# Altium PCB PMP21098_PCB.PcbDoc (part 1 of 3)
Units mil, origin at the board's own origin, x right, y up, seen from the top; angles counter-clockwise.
Board outline 5551.18 x 2125.98 mil, 4 copper layers (Top Layer, Signal Layer 1, Signal Layer 2, Bottom Layer), stack 61.6 mil thick; 197 components, 100 nets, 482 pads, 134 vias.
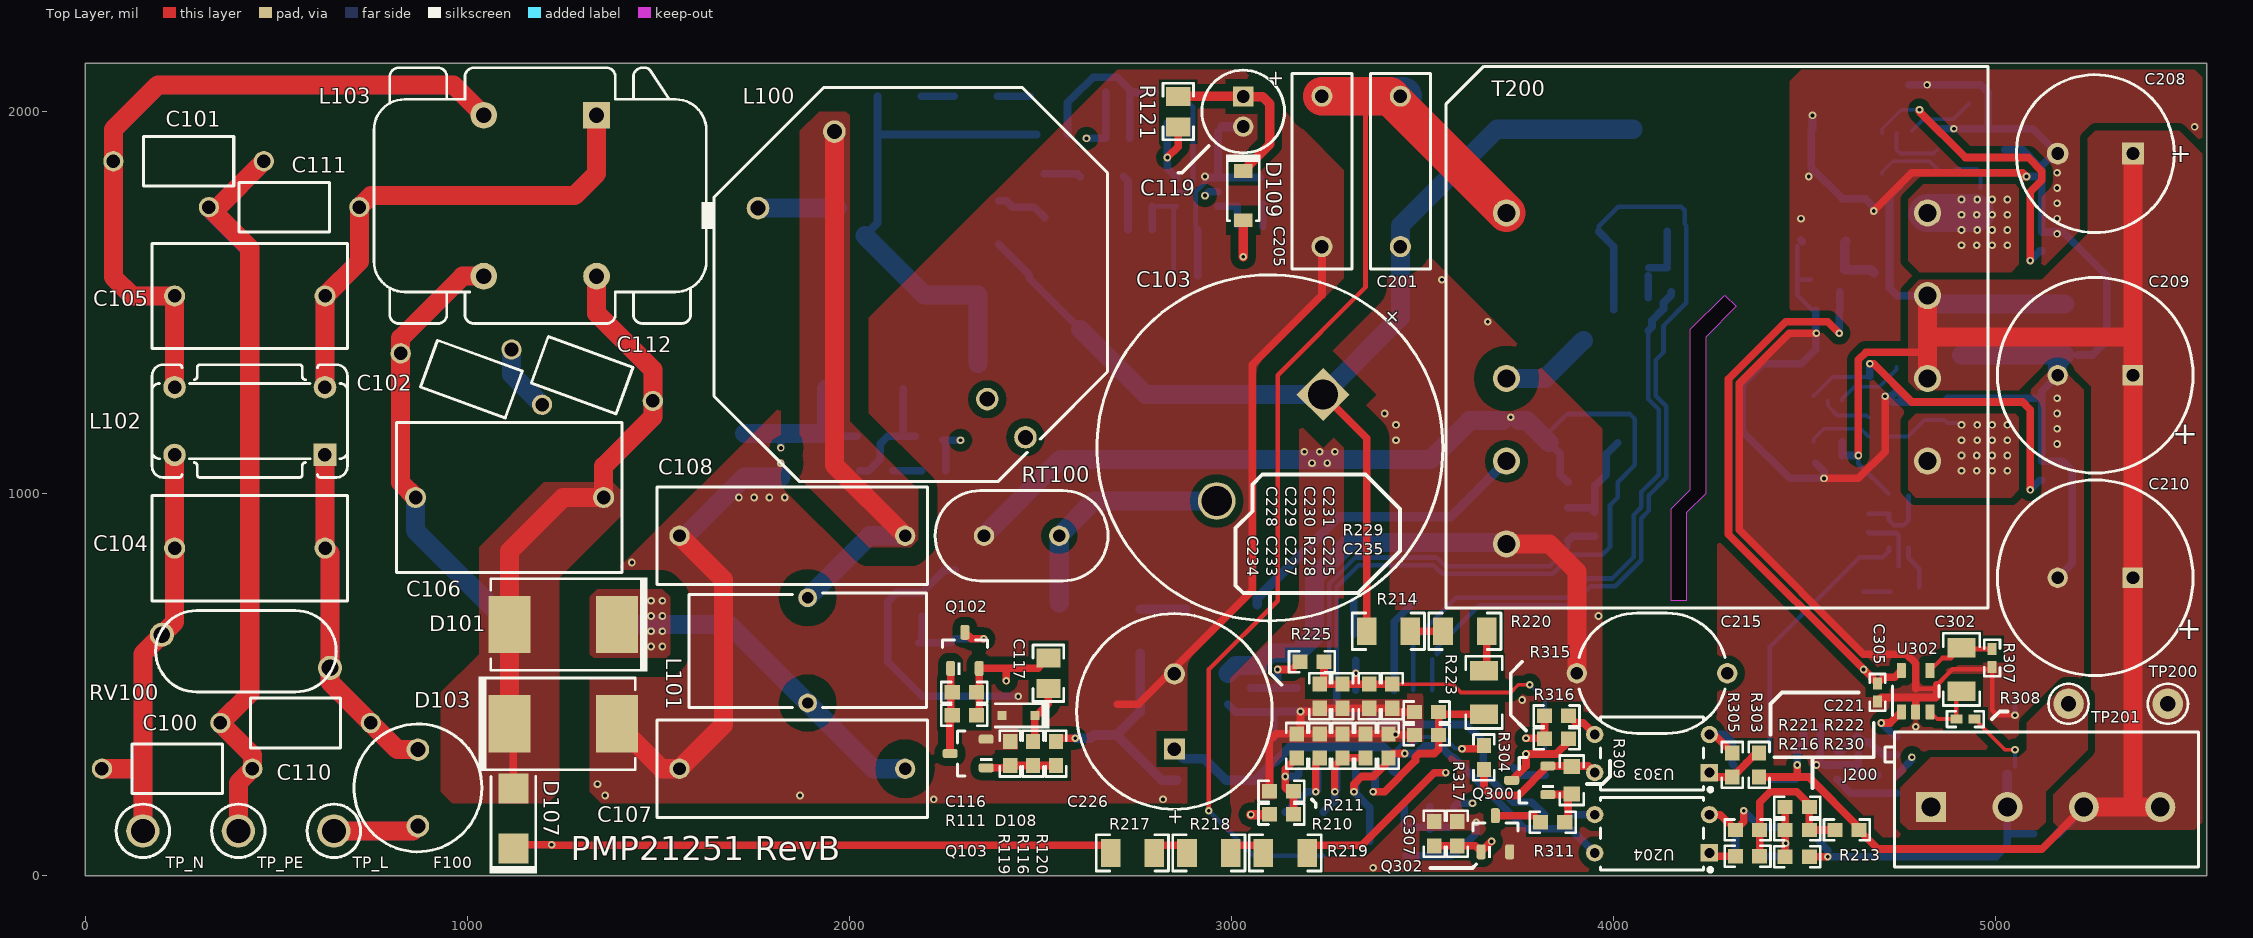
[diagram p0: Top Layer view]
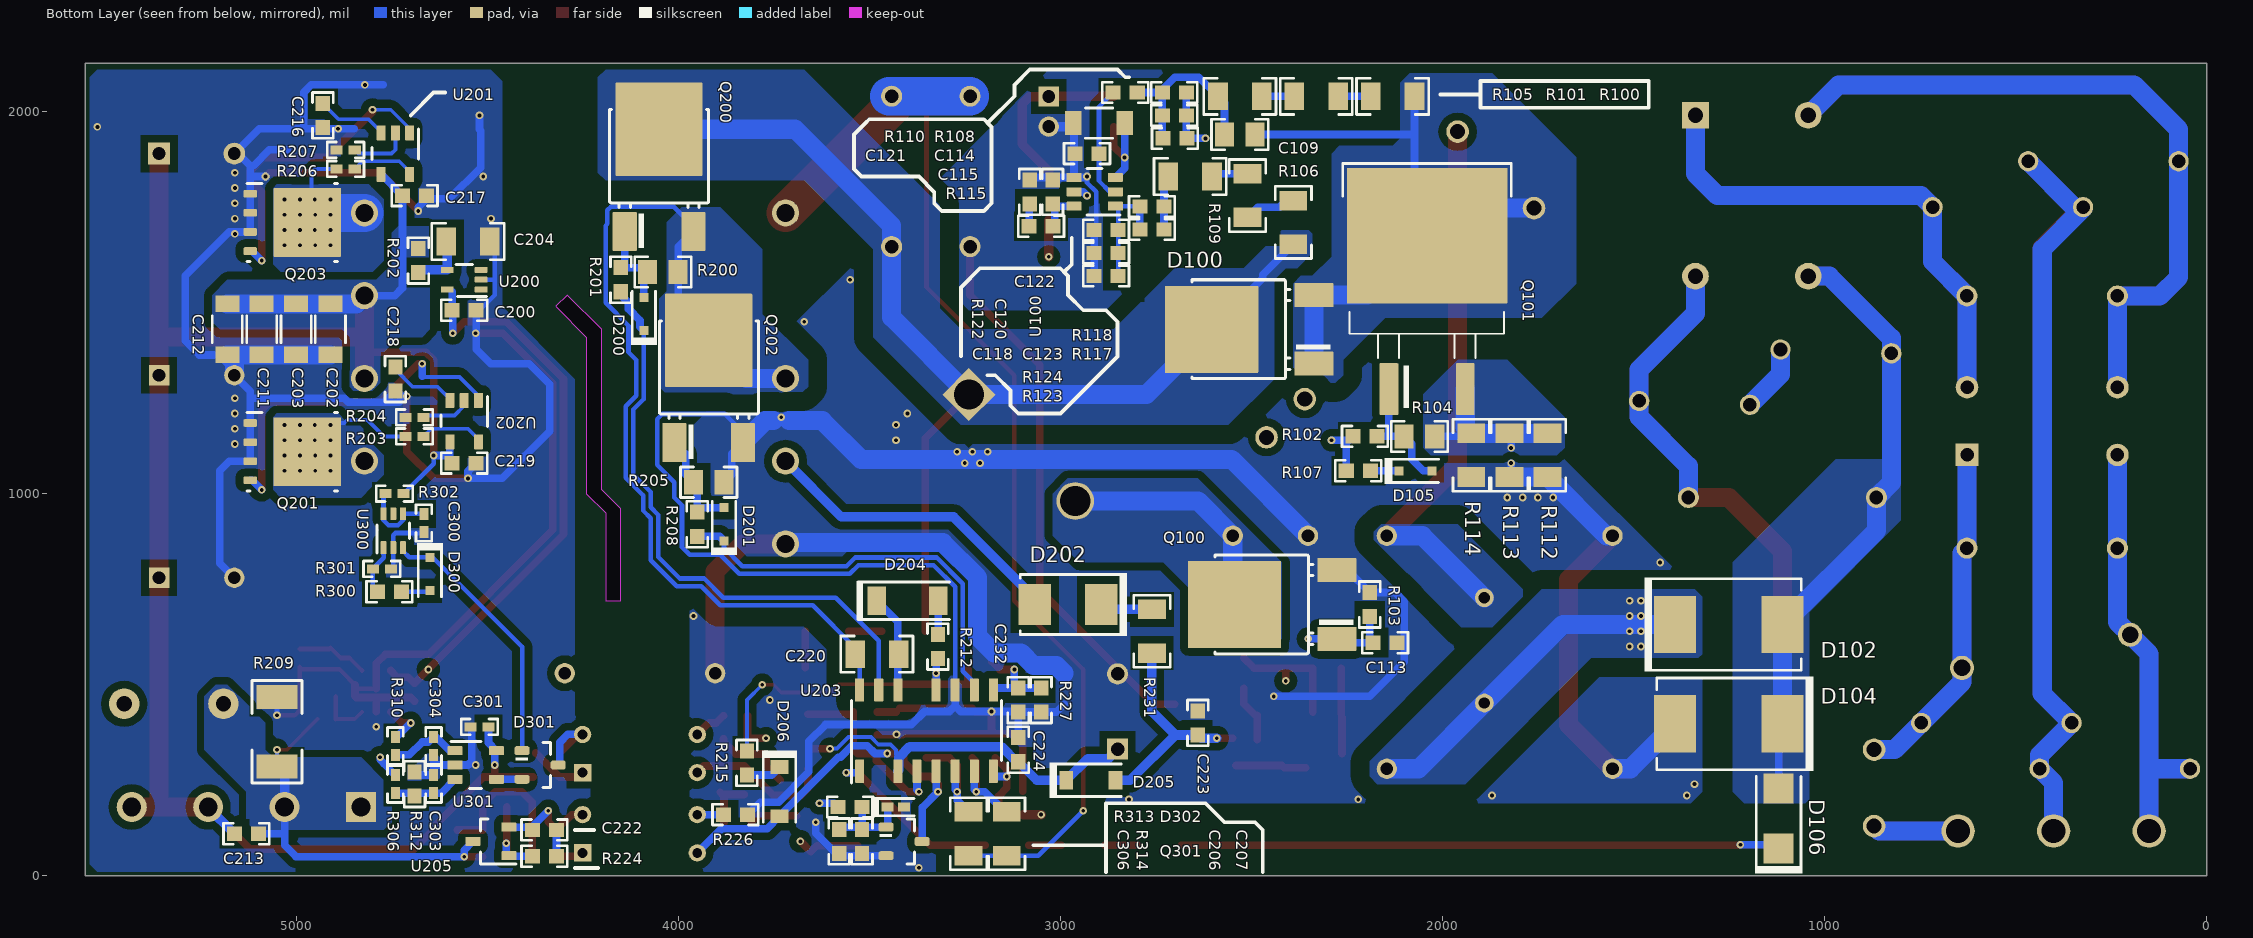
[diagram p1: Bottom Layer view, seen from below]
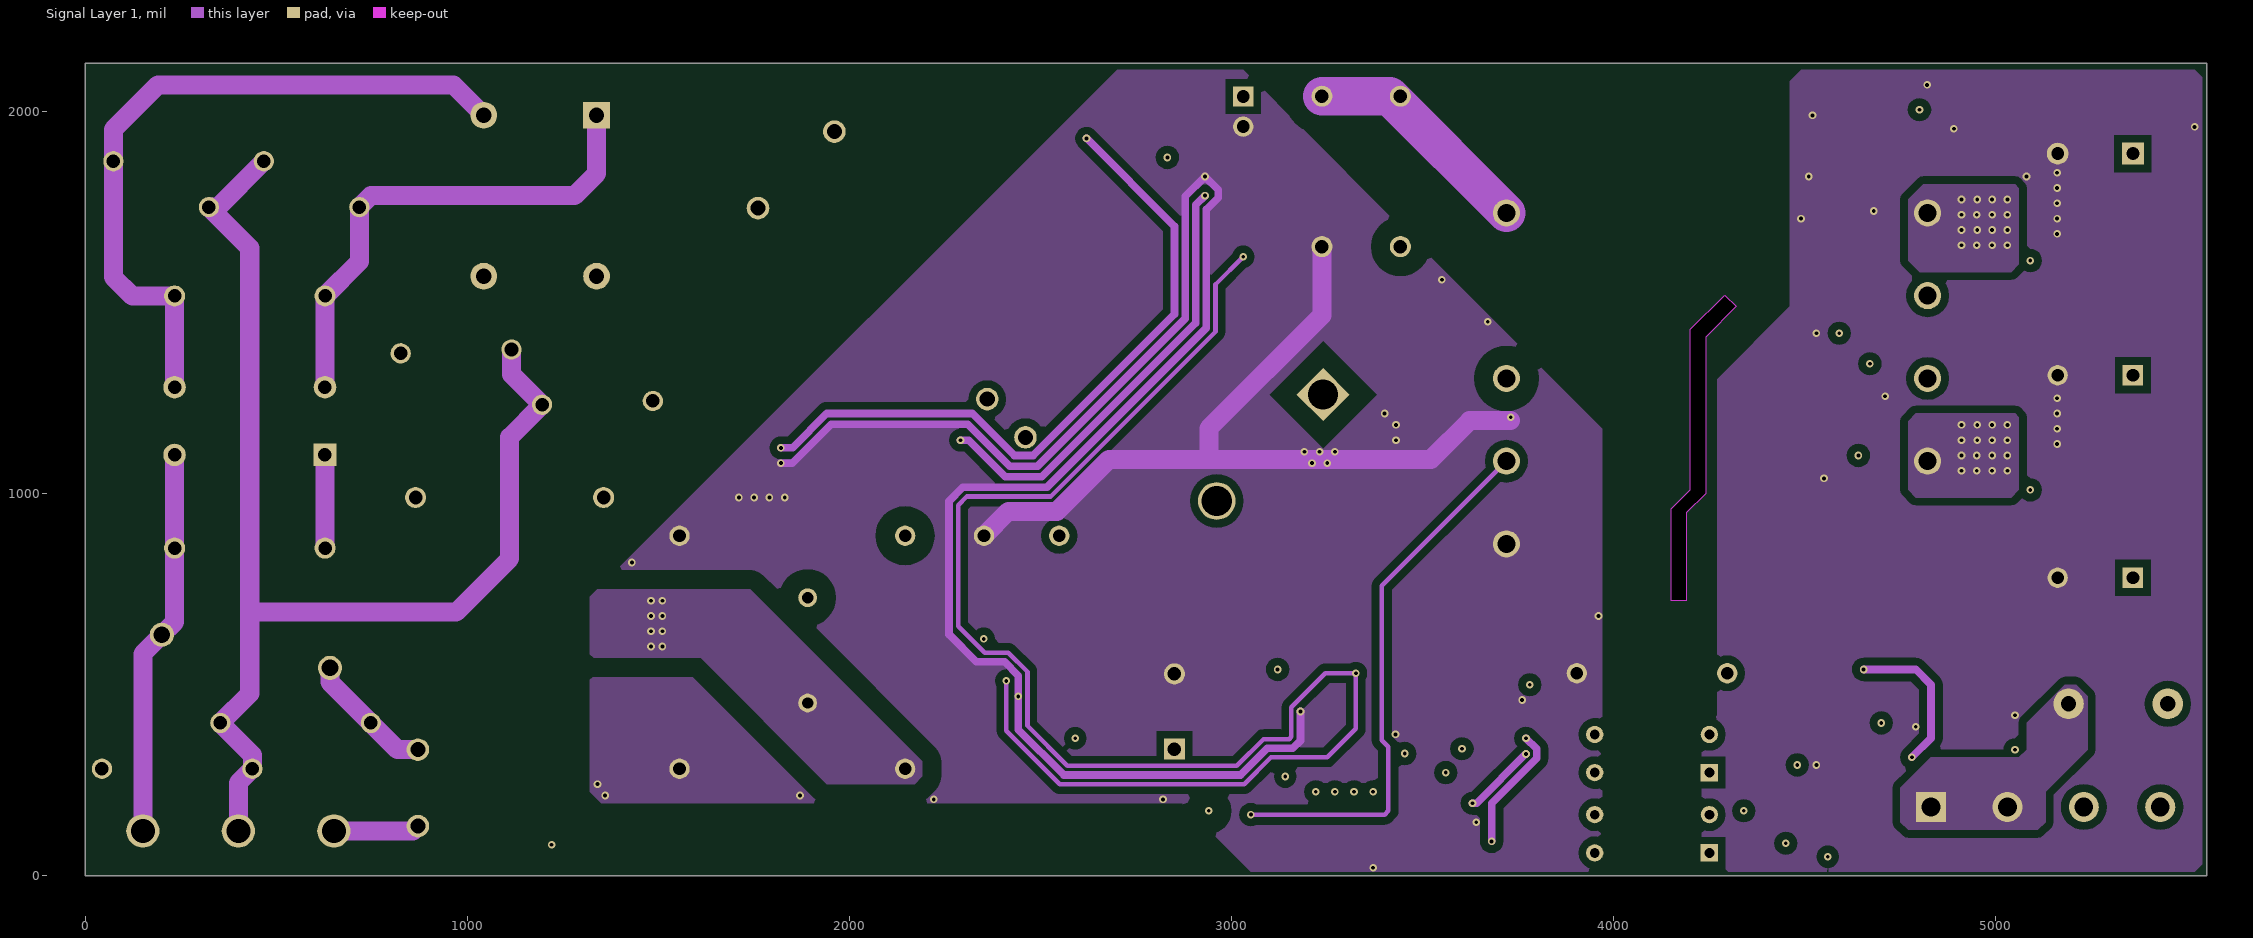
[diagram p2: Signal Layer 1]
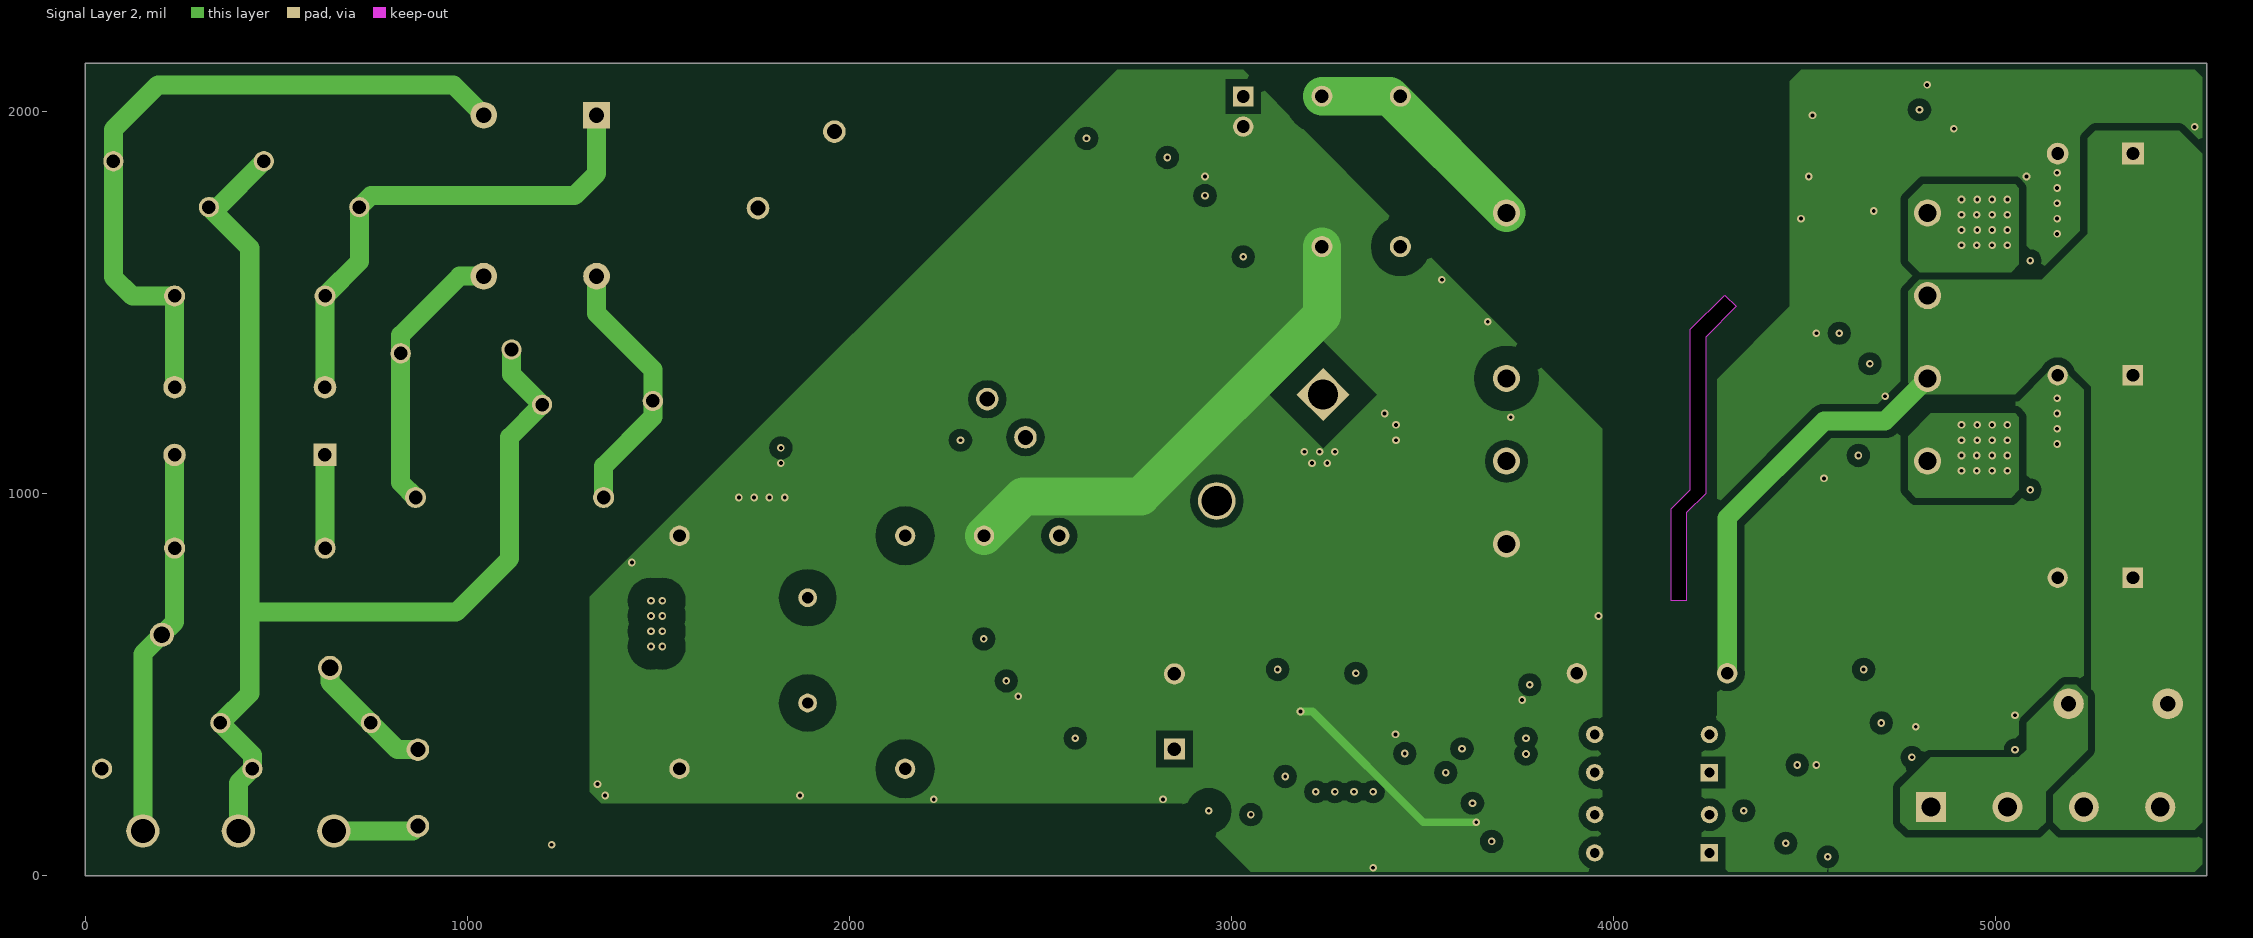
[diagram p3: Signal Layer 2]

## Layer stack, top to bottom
Top Solder: solder mask 0.4, Solder Resist, Dk 3.5
Top Layer: signal copper 1.4
Dielectric 2: prepreg 8, Dk 4.2
Signal Layer 1: signal copper 1.4
Dielectric1: core 40, FR-4, Dk 4.8
Signal Layer 2: signal copper 1.4
Dielectric 3: prepreg 8, Dk 4.2
Bottom Layer: signal copper 1.4
Bottom Solder: solder mask 0.4, Solder Resist, Dk 3.5

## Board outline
0,0 5551.18,0 5551.18,2125.98 0,2125.98
cut-out: 4150,720 4150,960 4200,1010 4200,1430 4290,1520 4320,1490 4240,1410 4240,1000 4190,950 4190,720

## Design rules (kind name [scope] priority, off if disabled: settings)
AcuteAngle [All] p1: minimum=4.50000000000000E+0001 checktracksonly=FALSE
AssemblyTestPointUsage [All] p1: valid=2
Clearance Clearance_2 [InNetClass('HV') vs Not InNetClass('HV')] p1: gap=50 ignorepadtopadclearanceinfootprint=FALSE except(0: Arc-Hole Track-Hole SMDPad-Hole THPad-Hole Via-Hole Fill-Hole Poly-Hole Region-Hole Text-Hole)
Clearance Clearance_1 [InNetClass('MV') vs Not InNetClass('MV')] p2: gap=20 ignorepadtopadclearanceinfootprint=FALSE
Clearance Clearance_Keepouts [((IsTrack Or IsArc) And Not InPoly) And IsFree and IsKeepOut vs ((IsTrack Or IsArc) And Not InPoly) And IsFree and IsKeepOut] p3: gap=0 ignorepadtopadclearanceinfootprint=FALSE
Clearance Clearance_BoardEdge_MountingHoles [OnCopper and InComponentClass('Mounting Holes') vs IsKeepOut] p4: gap=40 ignorepadtopadclearanceinfootprint=FALSE except(0: Arc-Hole Track-Hole SMDPad-Hole THPad-Hole Via-Hole Fill-Hole Poly-Hole Region-Hole Text-Hole)
Clearance Clearance_BoardEdge_Poly [OnCopper and InPoly vs IsKeepOut] p5: gap=25 ignorepadtopadclearanceinfootprint=FALSE except(0: Arc-Hole Track-Hole SMDPad-Hole THPad-Hole Via-Hole Fill-Hole Poly-Hole Region-Hole Text-Hole)
Clearance Clearance_BoardEdge [OnCopper and Not InComponentClass('Logo') and not InComponentClass('FiducialMark') and not InRegion(1000,500,4000,800) and Not IsKeepout vs IsKeepOut] p6: gap=75 ignorepadtopadclearanceinfootprint=FALSE except(0: Arc-Hole Track-Hole SMDPad-Hole THPad-Hole Via-Hole Fill-Hole Poly-Hole Region-Hole Text-Hole)
Clearance Clearance_Poly [InPolygon] p7: gap=20 ignorepadtopadclearanceinfootprint=FALSE except(0: Arc-Hole Track-Hole SMDPad-Hole THPad-Hole Via-Hole Fill-Hole Poly-Hole Region-Hole Text-Hole)
Clearance [All] p8: gap=7.87 ignorepadtopadclearanceinfootprint=FALSE except(0: Arc-Hole Track-Hole SMDPad-Hole THPad-Hole Via-Hole Fill-Hole Poly-Hole Region-Hole Text-Hole)
ComponentClearance ComponentClearance_MountingHoles_FiducialMarks [InComponentClass('Mounting Holes') vs InComponentClass('FiducialMark')] p1: gap=20 collisioncheckmode=3 verticalgap=10 showdistances=FALSE
ComponentClearance ComponentClearance_Shunt [InComponentClass('Header') vs InComponentClass('Shunt')] p2: gap=0 collisioncheckmode=3 verticalgap=0 showdistances=FALSE
ComponentClearance ComponentClearance_Logo [InComponentClass('Logo')] p3: gap=5 collisioncheckmode=3 verticalgap=10 showdistances=FALSE
ComponentClearance ComponentClearance_ScrewToNut [(HasFootprint('NY PMS 440 0025 PH')) vs (HasFootprint('Keystone_1902C'))] p4: gap=20 collisioncheckmode=3 verticalgap=100000 showdistances=FALSE
ComponentClearance ComponentClearance_MountingHoles [InComponentClass('Mounting Holes')] p5: gap=20 collisioncheckmode=3 verticalgap=10 showdistances=FALSE
ComponentClearance ComponentClearance_SmallPassives [HasFootprint('0201*') or HasFootprint('0402*') or HasFootprint('0508') or HasFootprint('0603*') or HasFootprint('0612') or HasFootprint('0805*') or HasFootprint('0815*') or HasFootprint('0830*') or HasFootprint('1206*') or HasFootprint('1210*') or HasFootprint('1808*') or HasFootprint('1812*') or HasFootprint('1825*') or HasFootprint('2010*') or HasFootprint('2220*') or HasFootprint('2225*') or HasFootprint('2512*') or HasFootprint('2728*') or HasFootprint('3518*') vs HasFootprint('0201*') or HasFootprint('0402*') or HasFootprint('0508') or HasFootprint('0603*') or HasFootprint('0612') or HasFootprint('0805*') or HasFootprint('0815*') or HasFootprint('0830*') or HasFootprint('1206*') or HasFootprint('1210*') or HasFootprint('1808*') or HasFootprint('1812*') or HasFootprint('1825*') or HasFootprint('2010*') or HasFootprint('2220*') or HasFootprint('2225*') or HasFootprint('2512*') or HasFootprint('2728*') or HasFootprint('3518*')] p6: gap=20 collisioncheckmode=3 verticalgap=20 showdistances=FALSE
ComponentClearance ComponentClearance_THtoSMT [IsThruComponent vs IsSMTComponent] p7: gap=10 collisioncheckmode=3 verticalgap=10 showdistances=FALSE
ComponentClearance ComponentClearance_THtoTH [IsThruComponent vs IsThruComponent] p8: gap=10 collisioncheckmode=3 verticalgap=10 showdistances=FALSE
ComponentClearance [All] p9: gap=10 collisioncheckmode=3 verticalgap=10 showdistances=FALSE
DiffPairsRouting [All] p1: maxlimit=100 minlimit=10 mostfreqgap=10 toplayer_minwidth=15 toplayer_maxwidth=15 toplayer_prefwidth=15 midlayer1_minwidth=15 midlayer1_maxwidth=15 midlayer1_prefwidth=15 midlayer2_minwidth=15 midlayer2_maxwidth=15 midlayer2_prefwidth=15 bottomlayer_minwidth=15 bottomlayer_maxwidth=15 bottomlayer_prefwidth=15 maxuncoupledlength=1000
FabricationTestPointUsage TestPointUsage [All] p1: valid=2 allowmultiple=FALSE
FabricationTestpoint Testpoint [All] p1: side=3 testpointundercomponent=TRUE minsize=40 maxsize=100 preferedsize=60 minholesize=0 maxholesize=40 preferedholesize=32 testpointgrid=1 allowsidetop=TRUE allowsidebottom=TRUE usegrid=TRUE gridtolerance=0.01
FanoutControl Fanout_LCC [IsLCC] p1: bgadir=Out bgaviamode=Centered fanoutstyle=Auto fanoutdirection=Alternating viagrid=1 // Fanout_LCC (Default Rule)
FanoutControl Fanout_BGA [IsBGA] p2: bgadir=Out bgaviamode=Centered fanoutstyle=Auto fanoutdirection=Alternating viagrid=1 // Fanout_BGA (Default Rule)
FanoutControl Fanout_Default [All] p4: bgadir=Out bgaviamode=Centered fanoutstyle=Auto fanoutdirection=Alternating viagrid=1 // Fanout_Default (Default Rule)
FanoutControl Fanout_Small [(CompPinCount < 5)] p5: bgadir=Out bgaviamode=Centered fanoutstyle=Auto fanoutdirection=OutThenIn viagrid=1 // Fanout_Small (Default Rule)
Height [All] p1: minheight=0 maxheight=3000 prefheight=500
HoleSize [All] p1: absolutevalues=TRUE maxlimit=251 minlimit=7 maxpercent=80.000 minpercent=20.000
MinimumAnnularRing MinimumAnnularRing_ThermalPadVias [IsVia and InAnyComponent] p1: minimumring=5.91
MinimumAnnularRing [All] p2: minimumring=4.9
MinimumSolderMaskSliver MinimumSolderMaskSliver_Logo [InComponentClass('Logo') vs InComponentClass('Logo')] p1: minsoldermaskwidth=0.7
MinimumSolderMaskSliver [All] p2: minsoldermaskwidth=2
PlaneConnect [All] p1: planeconnectstyle=Direct reliefexpansion=10 reliefentries=4 reliefconductorwidth=10 reliefairgap=10
PolygonConnect PolygonConnect_16 [All vs IsNamedPolygon('C106_2') Or  IsNamedPolygon('Vout') Or  IsNamedPolygon('IN+') Or  IsNamedPolygon('Q203_5') Or  IsNamedPolygon('IN+') Or  IsNamedPolygon('Q201_5') Or  IsNamedPolygon('C108_2') Or  IsNamedPolygon('SGND') Or  IsNamedPolygon('IN+') Or  IsNamedPolygon('SGND') Or  IsNamedPolygon('Q203_5') Or  IsNamedPolygon('IN+') Or  IsNamedPolygon('SGND') Or  IsNamedPolygon('GND') Or  IsNamedPolygon('C113_2') Or  IsNamedPolygon('C107_2') Or  IsNamedPolygon('C107_2') Or  IsNamedPolygon('Vout') Or  IsNamedPolygon('SIGNAL_LAYER_1_GND_P074') Or  IsNamedPolygon('HV') Or  IsNamedPolygon('C108_2') Or  IsNamedPolygon('C103_2') Or  IsNamedPolygon('Q201_5') Or  IsNamedPolygon('Vout') Or  IsNamedPolygon('C109_2') Or  IsNamedPolygon('Q201_5') Or  IsNamedPolygon('GND') Or  IsNamedPolygon('C107_2') Or  IsNamedPolygon('C102_1') Or  IsNamedPolygon('GND') Or  IsNamedPolygon('SGND') Or  IsNamedPolygon('HS') Or  IsNamedPolygon('Q203_5') Or  IsNamedPolygon('Q201_5') Or  IsNamedPolygon('Q203_5')] p1: connectstyle=Direct reliefconductorwidth=10 reliefentries=4 polygonreliefangle="90 Angle" airgapwidth=10
PolygonConnect PolygonConnect_15 [All vs IsNamedPolygon('C109_2') Or  IsNamedPolygon('C107_2') Or  IsNamedPolygon('HV') Or  IsNamedPolygon('Q203_5') Or  IsNamedPolygon('C107_2') Or  IsNamedPolygon('HS') Or  IsNamedPolygon('Q201_5') Or  IsNamedPolygon('Q203_5') Or  IsNamedPolygon('C106_2') Or  IsNamedPolygon('C108_2') Or  IsNamedPolygon('Vout') Or  IsNamedPolygon('Q203_5') Or  IsNamedPolygon('C108_2') Or  IsNamedPolygon('C113_2') Or  IsNamedPolygon('Q203_5') Or  IsNamedPolygon('Q201_5') Or  IsNamedPolygon('C107_2') Or  IsNamedPolygon('C102_1') Or  IsNamedPolygon('SGND') Or  IsNamedPolygon('GND') Or  IsNamedPolygon('SGND') Or  IsNamedPolygon('GND') Or  IsNamedPolygon('IN+') Or  IsNamedPolygon('IN+') Or  IsNamedPolygon('Q201_5') Or  IsNamedPolygon('Q201_5') Or  IsNamedPolygon('SGND') Or  IsNamedPolygon('SGND') Or  IsNamedPolygon('Vout') Or  IsNamedPolygon('Vout') Or  IsNamedPolygon('IN+') Or  IsNamedPolygon('GND') Or  IsNamedPolygon('IN+') Or  IsNamedPolygon('GND')] p2: connectstyle=Direct reliefconductorwidth=10 reliefentries=4 polygonreliefangle="90 Angle" airgapwidth=10
PolygonConnect PolygonConnect_14 [All vs IsNamedPolygon('C106_2') Or  IsNamedPolygon('C107_2') Or  IsNamedPolygon('C107_2') Or  IsNamedPolygon('C107_2') Or  IsNamedPolygon('C102_1') Or  IsNamedPolygon('Q203_5') Or  IsNamedPolygon('Vout') Or  IsNamedPolygon('Q203_5') Or  IsNamedPolygon('Q203_5') Or  IsNamedPolygon('Q201_5') Or  IsNamedPolygon('C108_2') Or  IsNamedPolygon('Q203_5') Or  IsNamedPolygon('HS') Or  IsNamedPolygon('HV') Or  IsNamedPolygon('C108_2') Or  IsNamedPolygon('Q201_5') Or  IsNamedPolygon('C109_2') Or  IsNamedPolygon('Q201_5') Or  IsNamedPolygon('Q201_5') Or  IsNamedPolygon('C113_2')] p3: connectstyle=Direct reliefconductorwidth=10 reliefentries=4 polygonreliefangle="90 Angle" airgapwidth=10
PolygonConnect PolygonConnect_13 [All vs IsNamedPolygon('C102_1') Or  IsNamedPolygon('HV') Or  IsNamedPolygon('C107_2') Or  IsNamedPolygon('C109_2') Or  IsNamedPolygon('C107_2') Or  IsNamedPolygon('C108_2') Or  IsNamedPolygon('C106_2') Or  IsNamedPolygon('C108_2') Or  IsNamedPolygon('C113_2') Or  IsNamedPolygon('C107_2')] p4: connectstyle=Direct reliefconductorwidth=10 reliefentries=4 polygonreliefangle="90 Angle" airgapwidth=10
PolygonConnect PolygonConnect_12 [All vs IsNamedPolygon('C107_2') Or  IsNamedPolygon('C113_2') Or  IsNamedPolygon('C106_2') Or  IsNamedPolygon('C107_2') Or  IsNamedPolygon('C107_2') Or  IsNamedPolygon('C102_1')] p5: connectstyle=Direct reliefconductorwidth=10 reliefentries=4 polygonreliefangle="90 Angle" airgapwidth=10
PolygonConnect PolygonConnect_11 [All vs IsNamedPolygon('C106_2') Or  IsNamedPolygon('C102_1') Or  IsNamedPolygon('C107_2') Or  IsNamedPolygon('C107_2') Or  IsNamedPolygon('C107_2')] p6: connectstyle=Direct reliefconductorwidth=10 reliefentries=4 polygonreliefangle="90 Angle" airgapwidth=10
PolygonConnect PolygonConnect_10 [All vs IsNamedPolygon('C106_2')] p7: connectstyle=Direct reliefconductorwidth=10 reliefentries=4 polygonreliefangle="90 Angle" airgapwidth=10
PolygonConnect PolygonConnect_9 [All vs IsNamedPolygon('C11_1') Or  IsNamedPolygon('Vin') Or  IsNamedPolygon('Vin') Or  IsNamedPolygon('5V') Or  IsNamedPolygon('D6_2') Or  IsNamedPolygon('Q3_3') Or  IsNamedPolygon('GND2') Or  IsNamedPolygon('GND2') Or  IsNamedPolygon('GND') Or  IsNamedPolygon('Q3_4') Or  IsNamedPolygon('12V5') Or  IsNamedPolygon('GND') Or  IsNamedPolygon('12V5') Or  IsNamedPolygon('D3_1')] p8: connectstyle=Direct reliefconductorwidth=10 reliefentries=4 polygonreliefangle="90 Angle" airgapwidth=10
PolygonConnect PolygonConnect_8 [All vs IsNamedPolygon('C11_1') Or  IsNamedPolygon('Vin') Or  IsNamedPolygon('12V5') Or  IsNamedPolygon('Q3_3') Or  IsNamedPolygon('GND2') Or  IsNamedPolygon('GND2') Or  IsNamedPolygon('5V') Or  IsNamedPolygon('Q3_4') Or  IsNamedPolygon('12V5')] p9: connectstyle=Direct reliefconductorwidth=10 reliefentries=4 polygonreliefangle="90 Angle" airgapwidth=10
PolygonConnect PolygonConnect_7 [All vs IsNamedPolygon('GND2') Or  IsNamedPolygon('GND2') Or  IsNamedPolygon('5V') Or  IsNamedPolygon('12V5') Or  IsNamedPolygon('12V5') Or  IsNamedPolygon('C11_1')] p10: connectstyle=Direct reliefconductorwidth=10 reliefentries=4 polygonreliefangle="90 Angle" airgapwidth=10
PolygonConnect PolygonConnect_6 [All vs IsNamedPolygon('GND2') Or  IsNamedPolygon('SGND') Or  IsNamedPolygon('GND1') Or  IsNamedPolygon('C901_1') Or  IsNamedPolygon('SGND') Or  IsNamedPolygon('GND2') Or  IsNamedPolygon('GND1')] p11: connectstyle=Direct reliefconductorwidth=10 reliefentries=4 polygonreliefangle="90 Angle" airgapwidth=10
PolygonConnect PolygonConnect_5 [All vs IsNamedPolygon('GND1') Or  IsNamedPolygon('GND1')] p12: connectstyle=Direct reliefconductorwidth=10 reliefentries=4 polygonreliefangle="90 Angle" airgapwidth=10
PolygonConnect PolygonConnect_4 [All vs IsNamedPolygon('C21_1') Or  IsNamedPolygon('C5_1') Or  IsNamedPolygon('C12_2') Or  IsNamedPolygon('C2_2') Or  IsNamedPolygon('C13_1') Or  IsNamedPolygon('C28_1') Or  IsNamedPolygon('C6_1') Or  IsNamedPolygon('GND') Or  IsNamedPolygon('GND2') Or  IsNamedPolygon('C14_1') Or  IsNamedPolygon('C13_1') Or  IsNamedPolygon('Q1_3') Or  IsNamedPolygon('C14_1') Or  IsNamedPolygon('C5_1') Or  IsNamedPolygon('GND2') Or  IsNamedPolygon('C28_1') Or  IsNamedPolygon('D5_2') Or  IsNamedPolygon('D6_2') Or  IsNamedPolygon('D2_1') Or  IsNamedPolygon('C12_2') Or  IsNamedPolygon('D2_1') Or  IsNamedPolygon('C4_1') Or  IsNamedPolygon('C4_1') Or  IsNamedPolygon('C2_2') Or  IsNamedPolygon('GND') Or  IsNamedPolygon('C33_1') Or  IsNamedPolygon('C9_1')] p13: connectstyle=Direct reliefconductorwidth=10 reliefentries=4 polygonreliefangle="90 Angle" airgapwidth=10
PolygonConnect PolygonConnect_3 [All vs IsNamedPolygon('C28_1') Or  IsNamedPolygon('C12_2') Or  IsNamedPolygon('C28_1') Or  IsNamedPolygon('C9_1') Or  IsNamedPolygon('D5_2') Or  IsNamedPolygon('C12_2') Or  IsNamedPolygon('C2_2') Or  IsNamedPolygon('C14_1') Or  IsNamedPolygon('C4_1') Or  IsNamedPolygon('C14_1') Or  IsNamedPolygon('D6_2') Or  IsNamedPolygon('GND2') Or  IsNamedPolygon('Q1_3') Or  IsNamedPolygon('C5_1') Or  IsNamedPolygon('D2_1') Or  IsNamedPolygon('C4_1') Or  IsNamedPolygon('C13_1') Or  IsNamedPolygon('C5_1') Or  IsNamedPolygon('C13_1') Or  IsNamedPolygon('C33_1') Or  IsNamedPolygon('D2_1') Or  IsNamedPolygon('GND') Or  IsNamedPolygon('GND') Or  IsNamedPolygon('GND2') Or  IsNamedPolygon('C2_2') Or  IsNamedPolygon('C6_1') Or  IsNamedPolygon('C21_1')] p14: connectstyle=Direct reliefconductorwidth=10 reliefentries=4 polygonreliefangle="90 Angle" airgapwidth=10
PolygonConnect PolygonConnect_2 [All vs IsNamedPolygon('C21_1') Or  IsNamedPolygon('C4_1') Or  IsNamedPolygon('D5_2') Or  IsNamedPolygon('C5_1') Or  IsNamedPolygon('C14_1') Or  IsNamedPolygon('C13_1') Or  IsNamedPolygon('C4_1') Or  IsNamedPolygon('C33_1') Or  IsNamedPolygon('C12_2') Or  IsNamedPolygon('D2_1') Or  IsNamedPolygon('C2_2') Or  IsNamedPolygon('C28_1') Or  IsNamedPolygon('C12_2') Or  IsNamedPolygon('D2_1') Or  IsNamedPolygon('C5_1') Or  IsNamedPolygon('Q1_3') Or  IsNamedPolygon('GND') Or  IsNamedPolygon('D6_2') Or  IsNamedPolygon('C6_1') Or  IsNamedPolygon('C2_2') Or  IsNamedPolygon('C14_1') Or  IsNamedPolygon('C28_1') Or  IsNamedPolygon('C13_1') Or  IsNamedPolygon('C9_1') Or  IsNamedPolygon('GND')] p15: connectstyle=Direct reliefconductorwidth=10 reliefentries=4 polygonreliefangle="90 Angle" airgapwidth=10
PolygonConnect PolygonConnect_1 [All vs IsNamedPolygon('C28_1') Or  IsNamedPolygon('D5_2') Or  IsNamedPolygon('C5_1') Or  IsNamedPolygon('C5_1') Or  IsNamedPolygon('D2_1') Or  IsNamedPolygon('C21_1') Or  IsNamedPolygon('C9_1') Or  IsNamedPolygon('C4_1') Or  IsNamedPolygon('C14_1') Or  IsNamedPolygon('C28_1') Or  IsNamedPolygon('C6_1') Or  IsNamedPolygon('C12_2') Or  IsNamedPolygon('C33_1') Or  IsNamedPolygon('C4_1') Or  IsNamedPolygon('C13_1') Or  IsNamedPolygon('C12_2') Or  IsNamedPolygon('D6_2') Or  IsNamedPolygon('C2_2') Or  IsNamedPolygon('C14_1') Or  IsNamedPolygon('D2_1') Or  IsNamedPolygon('C2_2') Or  IsNamedPolygon('C13_1')] p16: connectstyle=Direct reliefconductorwidth=10 reliefentries=4 polygonreliefangle="90 Angle" airgapwidth=10
PolygonConnect [All] p17: connectstyle=Relief reliefconductorwidth=10 reliefentries=4 polygonreliefangle="90 Angle" airgapwidth=10
RoutingVias ThermalPadVias [IsVia and InAnyComponent] p1: holewidth=7.87 width=19.68 viastyle="Through Hole" minholewidth=7.87 minwidth=19.68 maxholewidth=12.99 maxwidth=23.62
RoutingVias [All] p2: holewidth=16 width=34 viastyle="Through Hole" minholewidth=7.87 minwidth=20 maxholewidth=40 maxwidth=65
SilkToBoardRegionClearance [Not ((IsComment or IsDesignator) And (Hide <> 'False')) and not InRegion(1000,500,4000,800)] p1:
SilkToSilkClearance SilkToSilkClearance_Pb-FreeLogo [(HasFootprint('Pb-Free_Overlay_Medium') OR HasFootprint('Pb-Free_Overlay_Small')) vs (HasFootprint('Pb-Free_Overlay_Medium') OR HasFootprint('Pb-Free_Overlay_Small'))] p1: silktosilkclearance=0
SilkToSilkClearance [All] p2: silktosilkclearance=1
SilkToSolderMaskClearance "Silk to Solder Mask Opening" [All] p1: minsilkscreentomaskgap=1 clearancetoexposedcopper=FALSE
SolderMaskExpansion [All] p1: expansion=1.97
Width [All] p1: maxlimit=100 minlimit=6 preferedwidth=10 checkconnectedcopper=TRUE
14 further rules are at their usual default settings.

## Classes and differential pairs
component class PMP21098_BlankSheet: C200 C201 C202 C203 C204 C205 C206 C207 C208 C209 C210 C211 C212 C213 C215 C216 C217 C218 C219 C220 C221 C222 C223 C224 C225 C226 C227 C228 C229 C230 C231 C232 C233 C234 C235 D200 D201 D202 D204 D205 D206 J200 Q200 Q201 Q202 Q203 R200 R201 R202 R203 R204 R205 R206 R207 R208 R209 R210 R211 R212 R213 R214 R215 R216 R217 R218 R219 R220 R221 R222 R223 R224 R225 R226 R227 R228 R229 R230 R231 T200 TP200 TP201 U200 U201 U202 U203 U204 U205
component class PMP21098_EVM_Hardware: C300 C301 C302 C303 C304 C305 C306 C307 D300 D301 D302 Q300 Q301 Q302 R300 R301 R302 R303 R304 R305 R306 R307 R308 R309 R310 R311 R312 R313 R314 R315 R316 R317 U300 U301 U302 U303
net class HV: HO HS HV NetC101_1 NetC102_1 NetC104_2 NetC105_2 NetC106_2 NetC107_2 NetC108_2 NetC109_2 NetC201_2 NetC220_1 NetD200_2 XCAP
net class MV: NetD202_2 NetR100_1 NetR106_1 NetR109_1 NetR214_1 NetR220_1

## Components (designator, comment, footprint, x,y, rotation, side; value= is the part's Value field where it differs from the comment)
C100 "DE1B3RA101KN4AN01F" DE1_600x400x900 240,280 r0 top value=100pF
C101 "DE1B3RA101KN4AN01F" DE1_600x400x900 270,1870 r0 top value=220pF
C102 "DE1B3RA101KN4AN01F" DE1_600x400x900 1010,1300 r340 top value=220pF
C103 "EKMQ451VSN101MP30S" HXG_2200x4500 3100,1120 r225 top value=100uF
C104 "890324023023CS" WCAP-FTX2_1300x700x1200 430.13,857.51 r0 top value=0.1uF
C105 "890324023028CS" WCAP-FTX2_1300x700x1200 430.13,1517.51 r0 top value=0.22uF
C106 "890324024005" WCAP-FTX2_1500x1000x1600 1110,990 r0 top value=0.47uF
C107 "ECW-FD2W224KQ" MPK_1800x650 1850,280 r0 top value=0.22uF
C108 "450MPK474J" MPK_1800x650 1850,890 r0 top value=0.47uF
C109 "VJ0805A100JXGAT5Z" 0805_HV 2530,1940 r180 bottom value=10pF
C110 "DE1B3RA101KN4AN01F" DE1_600x400x900 550,400 r0 top value=100pF
C111 "DE1B3RA101KN4AN01F" DE1_600x400x900 520,1750 r0 top value=220pF
C112 "DE1B3RA101KN4AN01F" DE1_600x400x900 1300,1310 r340 top value=220pF
C113 "GRM188R61E104KA01D" 0603 2150,610 r180 bottom value=0.1uF
C114 "06031C332JAT2A" 0603 2701.5,1990 r180 bottom value=3300pF
C115 "GRM1885C1H681JA01D" 0603 2700,1930 r180 bottom value=680pF
C116 "885012206040" 0603 2300,480 r180 top value=0.01uF
C117 "08053D474KAT2A" 0805_HV 2520,530 r270 top value=0.47uF
C118 "C0603C105K3RACTU" 0603 3050,1700 r0 bottom value=1uF
C119 "ECA-1HHG100" NHG_500x1100 3030,2000 r270 top value=10uF
C120 "C0603C333J3RACTU" 0603 3020,1790 r90 bottom value=0.033uF
C121 "CGA5L2X7R1H474K160AA" 1206_180 2898.5,1970 r0 bottom value=0.47uF
C122 "0603ZC100KAT2A" 0603 2930,1890 r0 bottom value=10pF
C123 "C0603C222K5RACTU" 0603 2880,1690 r0 bottom value=2200pF
C200 "C0603C105K4PACTU" 0603 4560,1480 r180 bottom value=1uF
C201 "B32621A6103K189" B32021_1300x400x900 3441.39,1843.42 r90 top value=0.01uF
C202 "EMK316BB7226ML-T" 1206_190 4910,1430 r90 bottom value=22uF
C203 "EMK316BB7226ML-T" 1206_190 5000,1430 r90 bottom value=22uF
C204 "GRM319R61E105KC36D" 1206 4550,1660 r180 bottom value=1uF
C205 "B32621A6103K189" B32021_1300x400x900 3236.03,1843.42 r270 top value=0.01uF
C206 "GRM31A5C2J151JW01D" 1206 3240,110 r270 bottom value=150pF
C207 "GRM31A5C2J151JW01D" 1206 3140,110 r90 bottom value=150pF
C208 "APSC160ELL471MJB5S" PS_1000x1250 5260,1890 r180 top value=470uF
C209 "EEU-FM1C222" HW_1250x2000 5260,1310 r180 top value=2200uF
C210 "EEU-FM1C222" HW_1250x2000 5260,780 r180 top value=2200uF
C211 "EMK316BB7226ML-T" 1206_190 5090,1430 r270 bottom value=22uF
C212 "EMK316BB7226ML-T" 1206_190 5180,1430 r270 bottom value=22uF
C213 "C0603C105K4PACTU" 0603 5130,110 r0 bottom value=1uF
C215 "DE1E3KX222MA5BA01" CAPRD1000W60D1000H1400 4100,530 r180 top value=2200pF
C216 "885012106018" 0603 4930,1990 r270 bottom value=2.2uF
C217 "06033C104JAT2A" 0603 4690,1780 r180 bottom value=0.1uF
C218 "885012106018" 0603 4740,1300 r270 bottom value=2.2uF
C219 "06033C104JAT2A" 0603 4560,1080 r180 bottom value=0.1uF
C220 "C1206C225K4RACTU" 1206 3480,580 r0 bottom value=2.2uF
C221 "06035A101JAT2A" 0603 4480,180 r180 top value=100pF
C222 "06033C473JAT2A" 0603 4350,120 r0 bottom value=0.047uF
C223 "GRM188R6YA225KA12D" 0603 2640,400 r270 bottom value=2.2uF
C224 "GRM188R6YA225KA12D" 0603 3110,330 r270 bottom value=2.2uF
C225 "GRM1885C1H470FA01J" 0603 3410,340 r90 top value=47pF
C226 "EEU-FR1V102B" B41896_1250x2500 2850,430 r90 top value=1000uF
C227 "GRM1885C1H332JA01D" 0603 3290,340 r270 top value=3300pF
C228 "GRM188R61C475KAAJ" 0603 3230,470 r270 top value=4.7uF
C229 "GRM188R61C475KAAJ" 0603 3290,470 r270 top value=4.7uF
C230 "GRM188R61C475KAAJ" 0603 3360,470 r270 top value=4.7uF
C231 "06031C103JAT2A" 0603 3420,470 r270 top value=0.01uF
C232 "C1608X7R1H473K080AA" 0603 3110,460 r270 bottom value=0.047uF
C233 "C0603C123J3GACTU" 0603 3230,340 r90 top value=0.012uF
C234 "06035A2R2CAT2A" 0603 3170,340 r90 top value=2.2pF
C235 "GRM188R71H221KA01D" 0603 3510,368.7 r180 top value=220pF
C300 "GRM155R61C104KA88D" 0402 4665.61,923.27 r270 bottom value=0.1uF
C301 "GRM155R61C104KA88D" 0402 4520,390 r0 bottom value=0.1uF
C302 "12067A470JAT2A" 1206 4910,540 r90 top value=47pF
C303 "GRM1555C1H100RA01D" 0402 4640,240 r90 bottom value=10pF
C304 "GRM1555C1H101JA01D" 0402 4640,340 r270 bottom value=100pF
C305 "GRM155R61E104KA87D" 0402 4690,480 r270 top value=0.1uF
C306 "C0603C103J3GECAUTO" 0603 3578.7,90 r270 bottom value=0.01uF
C307 "C0603C223K5RACTU" 0603 3530,110 r90 top value=0.022uF
D100 "STTH5L06B-TR" DPAK 2470,1430 r0 bottom value=600V
D101 "S5J-E3/57T" SMC 1250.12,657.51 r180 top value=600V
D102 "S5J-E3/57T" SMC 1250.13,657.51 r180 bottom value=600V
D103 "S5J-E3/57T" SMC 1250.13,397.51 r0 top value=600V
D104 "S5J-E3/57T" SMC 1250.13,397.51 r0 bottom value=600V
D105 "MMDL914-TP" SOD-323 2070,1060 r180 bottom value=100V
D106 "MURA160T3G" SMA 1120,150 r90 bottom value=1.05V
D107 "MURA160T3G" SMA 1120,150 r90 top value=1.05V
D108 "MMDL914-TP" SOD-323 2441.47,420 r180 top value=100V
D109 "1N4148WFL-G3-08" SOD-123FL 3030,1780 r270 top value=100V
D200 "MMDL914-TP" SOD-323 4090,1470 r90 bottom value=100V
D201 "MMDL914-TP" SOD-323 3880,920 r90 bottom value=100V
D202 "STPS160UY" SMB 2980,710 r0 bottom value=60V
D204 "ES1JAF" SMAF 3400,720 r180 bottom value=600V
D205 "1N4148W-7-F" SOD-123 2920,250 r180 bottom value=100V
D206 "MMSZ5234B-7-F" SOD-123 3734.92,220 r270 bottom value=6.2V
D300 "BAT42WS" sod-323 4650,790 r270 bottom value=1V
D301 "BAS70-06-7-F" SOT-23 4361.3,290 r180 bottom value=70V
D302 "MM5Z15VT1G" SOD-523 3430,180 r180 bottom value=15V
F100 "37213150001" FUSE_372 870,230 r90 top
J200 "ED120/4DS" On-Shore_ED120_4DS 5130,180 r0 top
L100 "750316570" 750316570 2160.13,1547.51 r0 top value=200uH
L101 "7447021" IND_7447020 1890,590 r90 top value=100µH
L102 "744821201" WE-CMB_XS 430,1190 r180 top value=1mH
L103 "744823210" WE-CMB_M 1190,1780 r270 top value=10mH
Q100 "STD13NM60ND" DPAK 2410,710 r0 bottom value=600V
Q101 "IPB60R199CP" DDPAK 2040,1520 r90 bottom value=600V
Q102 "MMBT4403" SOT-23 2301.65,590 r90 top value="40 V"
Q103 "MMBT4401-7-F" SOT-23 2310,320 r180 top value="40 V"
Q200 "STD16N50M2" DPAK 4050,1820 r90 bottom value=550V
Q201 "CSD18504Q5A" DQJ0008A 5010,1110 r180 bottom value=40V
Q202 "STD16N50M2" DPAK 3920.13,1267.51 r90 bottom value=550V
Q203 "CSD18504Q5A" DQJ0008A 5010,1710 r180 bottom value=40V
Q300 "MMBT3906" SOT-23 3780,250 r180 top value="40 V"
Q301 "2N7002ET1G" SOT-23 3408.7,90 r180 bottom value=60V
Q302 "MMBT4401-7-F" SOT-23 3690,110 r90 top value="40 V"
R100 "CRCW12063M24FKEA" 1206 2130,2040 r180 bottom value=3.24Meg
R101 "CRCW12063M24FKEA" 1206 2330,2040 r180 bottom value=3.24Meg
R102 "CRCW060310R0FKEA" 0603 2202.53,1150 r180 bottom value=10.0
R103 "CRCW06031M00FKEA" 0603 2190,710 r270 bottom value=1.00Meg
R104 "CRCW080520K0FKEA" 0805_HV 2060,1150 r0 bottom value=20.0k
R105 "CRCW12063M24FKEA" 1206 2530,2040 r180 bottom value=3.24Meg
R106 "CRCW12063M24FKEA" 1206 2390,1710 r270 bottom value=3.24Meg
R107 "CRCW06031R00FKEA" 0603 2220,1060 r180 bottom value=1.00
R108 "CRCW060324K3FKEA" 0603 2701.5,2050 r0 bottom value=24.3k
R109 "CRCW12063M24FKEA" 1206 2510,1780 r270 bottom value=3.24Meg
R110 "CRCW06033K00JNEA" 0603 2830,2050 r0 bottom value=3.0k
R111 "CRCW060310K0FKEA" 0603 2300,420 r0 top value=10.0k
R112 "CSR1206FTR130" 1206 1724.45,1100.71 r90 bottom value=0.13
R113 "CSR1206FTR130" 1206 1824.45,1100.71 r90 bottom value=0.13
R114 "CRCW1206453KFKEA" 1206 1924.45,1100.71 r90 bottom value=453k
R115 "CRCW12063M24FKEA" 1206 2660,1830 r180 bottom value=3.24Meg
R116 "CRCW060375K0FKEA" 0603 2480,320 r90 top value=75.0k
R117 "CRCW060336K5FKEA" 0603 2760,1691.46 r180 bottom value=36.5k
R118 "RC0603FR-07120KL" 0603 2760,1751.46 r180 bottom value=120k
R119 "CRCW060349K9FKEA" 0603 2420,320 r270 top value=49.9k
R120 "RC0603FR-07390KL" 0603 2540,320 r270 top value=390k
R121 "CRCW080510R0FKEA" 0805_HV 2860,2000 r90 top value=10.0
R122 "RC0603FR-07180KL" 0603 3080,1790 r270 bottom value=180k
R123 "CRCW060375K0FKEA" 0603 2880,1570 r180 bottom value=75.0k
R124 "RC0603FR-07390KL" 0603 2880,1630 r180 bottom value=390k
R200 "CRCW080510K0FKEA" 0805_HV 4040,1580 r0 bottom value=10.0k
R201 "CRCW060310R0FKEA" 0603 4150,1560 r90 bottom value=10.0
R202 "CRCW06030000Z0EA" 0603 4680,1610 r90 bottom value=0
R203 "CRCW04020000Z0ED" 0402 4690,1150 r0 bottom value=0
R204 "CRCW04020000Z0ED" 0402 4690,1200 r0 bottom value=0
R205 "CRCW080510K0FKEA" 0805_HV 3920,1030 r0 bottom value=10.0k
R206 "CRCW04020000Z0ED" 0402 4870,1850 r180 bottom value=0
R207 "CRCW04020000Z0ED" 0402 4870,1900 r180 bottom value=0
R208 "CRCW060310R0FKEA" 0603 3950,920 r90 bottom value=10.0
R209 "CSNL2010FT1L00" 2010 5050,376.85 r270 bottom value=0.001
R210 "CRCW060336K5FKEA" 0603 3130,161.3 r180 top value=36.5k
R211 "RC0603FR-078K45L" 0603 3130,221.3 r0 top value=8.45k
R212 "CRCW06032R20JNEA" 0603 3320,600 r90 bottom value=2.2
R213 "CRCW060320R0FKEA" 0603 4610,120 r180 top value=20.0
R214 "CRCW12064M99FKEA" 1206 3410,640 r180 top value=4.99Meg
R215 "ERJ-3EKF1002V" 0603 3820,295.26 r90 bottom value=10.0k
R216 "CRCW06031K50FKEA" 0603 4350,51.1 r0 top value=1.50k
R217 "CRCW12061K65FKEA" 1206 2740,60 r180 top value=1.65k
R218 "CRCW12061K65FKEA" 1206 2940,60 r180 top value=1.65k
R219 "CRCW12061K65FKEA" 1206 3140,60 r180 top value=1.65k
R220 "CRCW12064M99FKEA" 1206 3610,640 r180 top value=4.99Meg
R221 "CRCW06036K04FKEA" 0603 4350,120 r0 top value=6.04k
R222 "CRCW0603150KFKEA" 0603 4480,120 r0 top value=150k
R223 "CRCW12064M99FKEA" 1206 3660,480 r90 top value=4.99Meg
R224 "CRCW060325K5FKEA" 0603 4350,51.1 r0 bottom value=25.5k
R225 "CRCW0603806KFKEA" 0603 3210,560 r0 top value=806k
R226 "CRCW06030000Z0EA" 0603 3850,160 r0 bottom value=0
R227 "CRCW0603150KFKEA" 0603 3050,460 r90 bottom value=150k
R228 "CRCW060368R1FKEA" 0603 3350,340 r270 top value=68.1
R229 "CRCW060344K2FKEA" 0603 3510,428.7 r0 top value=44.2k
R230 "CRCW060317K4FKEA" 0603 4480,50 r180 top value=17.4k
R231 "CRCW120649R9FKEA" 1206 2760,640 r90 bottom value=49.9
R300 "CRCW06032M21FKEA" 0603 4755.61,743.27 r0 bottom value=2.21Meg
R301 "CRCW0402619KFKED" 0402 4775.61,803.27 r0 bottom value=619k
R302 "ERJ-2GE0R00X" 0402 4742.44,1000 r0 bottom value=0
R303 "CRCW060310K0FKEA" 0603 4380,290 r270 top value=10.0k
R304 "CRCW06030000Z0EA" 0603 3660,310 r270 top value=0
R305 "CRCW060310K0FKEA" 0603 4310,290 r270 top value=10.0k
R306 "CRCW0402100KFKED" 0402 4740,240 r90 bottom value=100k
R307 "CRCW04024R75FKED" 0402 4990,570 r270 top value=4.75
R308 "CRCW04024R75FKED" 0402 4920,410 r0 top value=4.75
R309 "CPF0603B2K0E" CPF0603 3890,250 r90 top value=2.00k
R310 "ATC504L1000FTNCFT" 0402 4740,340 r270 bottom value=100
R311 "RC0603FR-077K5L" 0603 3840,140 r0 top value=7.50k
R312 "CRCW0603432KFKEA" 0603 4690,240 r270 bottom value=432k
R313 "RC0603JR-072KL" 0603 3550,180 r180 bottom value=2.0k
R314 "CRCW06032M20JNEA" 0603 3518.7,90 r90 bottom value=2.2Meg
R315 "CRCW060330K1FKEA" 0603 3850,358.54 r0 top value=30.1k
R316 "CRCW060341K2FKEA" 0603 3850,418.54 r0 top value=41.2k
R317 "CRCW060341K2FKEA" 0603 3590,110 r270 top value=41.2k
RT100 "B57236S0100M000" THERM_B57236S0 2450,890 r0 top value="10 ohm"
RV100 "S10K275E2" VAR_S10K275E2 420.13,587.51 r180 top
T200 "760895431" Wurth_ETD34 4270,1410 r0 top value=600uH
TP200 "5000" Keystone5000 5450,450 r90 top
TP201 "5001" Keystone5001 5190,450 r0 top
TP_L "5010" Keystone5010 650.13,117.51 r90 top
TP_N "5011" Keystone5011 150.13,117.51 r0 top
TP_PE "5012" Keystone5012 400.13,117.51 r0 top
U100 "UCC28056DBV" DBV0006A_N 2910,1790 r0 bottom
U200 "TPS71550DCKR" DCK0005A_N 4560,1560 r0 bottom
U201 "UCC24612-2DBVR" DBV0005A_N 4740,1890 r270 bottom
U202 "UCC24612-2DBVR" DBV0005A_N 4560,1190 r270 bottom
U203 "UCC256304DDB" DDB0014A 3350,380 r90 bottom
U204 "VO618A-3" DIP-4 4100,110 r180 top
U205 "TLVH431AQDBZR" DBZ0003A_N 4490,90 r0 bottom
U300 "TMP300BIDCKR" DCK0006A_N 4745.61,903.27 r90 bottom
U301 "TL331IDBVR" DBV0005A_N 4530,290 r180 bottom
U302 "INA180A4IDBV" DBV0005A_N 4790,483.15 r90 top
U303 "FOD817D" DIP-4 4100,320 r180 top

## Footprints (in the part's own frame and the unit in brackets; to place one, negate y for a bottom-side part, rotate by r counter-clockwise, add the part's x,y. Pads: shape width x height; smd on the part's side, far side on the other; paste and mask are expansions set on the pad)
0402 [mm] "0402 from SM-752 data"
  rect 0.8x0.6 smd: 1(-0.6,0) 2(0.6,0)
  silkscreen extent -1.22,-0.52 1.22,0.52, body extent -0.55,-0.3 0.55,0.3, height 0.6
0603 [mm] "0603 from SM-752 data"
  rect 1x0.95 smd: 1(-0.8,0) 2(0.8,0)
  silkscreen extent -1.52,-0.69 1.52,0.69, body extent -0.87,-0.47 0.87,0.47, height 1
0805_HV [mil] "0805 with 30mil clearance between pads"
  rect 50x63 smd: 1(-40,0) 2(40,0)
  silkscreen extent -74,-40 74,40, body extent -43,-29 43,29, height 57
1206 [mm] "1206 from SM-752 data"
  rect 1.3x1.85 smd: 1(-1.45,0) 2(1.45,0)
  silkscreen extent -2.4,-1.21 2.4,1.21, body extent -1.7,-0.9 1.7,0.9, height 1.35
1206_180 [mm] "1206_180"
  rect 1.1x1.6 smd: 1(-1.7,0) 2(1.7,0)
  silkscreen extent -0.9,-1 0.9,1, body extent -1.75,-0.95 1.75,0.95, height 1.8
1206_190 [mm] "1206_190"
  rect 1.1x1.6 smd: 1(-1.7,0) 2(1.7,0)
  silkscreen extent -0.9,-1 0.9,1, body extent -1.75,-0.95 1.75,0.95, height 1.9
2010 [mm] "Chip Capacitor, Body 5.08x2.54mm, IPC Medium Density"
  rect 1.6x2.7 smd: 1(-2.3,0) 2(2.3,0)
  silkscreen extent -3.42,-1.65 3.42,1.65, body extent -2.73,-1.45 2.73,1.45, height 1.66
750316570 [mm] "TH, 5-Leads, Body 26.16x26.16mm"
  round 1.5 hole 1: 2(-10.16,5.08) 4(5.08,-7.62) 6(7.62,-10.16) 11(-5.08,10.16)
  silkscreen extent -13.9,-13.08 13.08,13.08, body extent -13.08,-13.08 13.08,13.08, height 19.05
B32021_1300x400x900 [mm] "TH, 2-Leads, Body 13x4mm, Lead Spacing 10mm"
  round 1.4 hole 0.9: 1(-5,0) 2(5,0)
  silkscreen extent -6.5,-2 6.5,2, body extent -6.5,-2 6.5,2, height 9
B41896_1250x2500 [mm] "TH, 2-Leads, Dia 12.5mm, Pin Spacing 5mm"
  rect 1.4x1.4 hole 0.9: 1(-2.5,0)
  round 1.4 hole 0.9: 2(2.5,0)
  silkscreen extent -6.5,-6.5 6.5,6.5, body extent -6.5,-6.5 6.51,6.5, height 27.01
CAPRD1000W60D1000H1400 [mm] "Disk, Radial Capacitor"
  round 1.35 hole 0.85: 1(-5,0) 2(5,0)
  silkscreen extent -4.86,-4 4.86,4, body extent -5.67,-4 5.7,4, height 13.99
CPF0603 [mm] "TE Connectivity"
  rect 1x1.1 smd: 1(-0.9,0) 2(0.9,0)
  silkscreen extent -1.65,-0.8 1.65,0.8, body extent -0.82,-0.45 0.82,0.45, height 0.55
DBV0005A_N [mm] "SOT23, 5-Leads, Body 2.9x1.6mm, Pitch 0.95mm, Lead Span 2.8mm, IPC Medium Density"
  rrect17% 1x0.6 smd: 1(-1.375,0.95) 2(-1.375,0) 3(-1.375,-0.95) 4(1.375,-0.95) 5(1.375,0.95)
  silkscreen extent -1.63,-1.55 0.38,1.55, body extent -1.42,-1.46 1.42,1.46, height 1.09
DBV0006A_N [mm] "SOT23, 6-Leads, Body 2.9x1.6mm, Pitch 0.95mm, Lead Span 2.8mm, IPC Medium Density"
  rrect17% 1x0.6 smd: 1(-1.375,0.95) 2(-1.375,0) 3(-1.375,-0.95) 4(1.375,-0.95) 5(1.375,0) 6(1.375,0.95)
  silkscreen extent -1.68,-1.55 0.5,1.55, body extent -1.42,-1.46 1.42,1.46, height 1.12
DBZ0003A_N [mm] "SOT23, 3-Leads, Body 2.9x1.3mm, Pitch 0.95mm, Lead Span 2.4mm, IPC Medium Density"
  rrect17% 1x0.6 smd: 1(-1.2,0.95) 2(-1.2,-0.95) 3(1.2,0)
  silkscreen extent -1.65,-1.5 0.7,1.5, body extent -1.26,-1.46 1.26,1.46, height 0.98
DCK0005A_N [mm] "SOT353, 5-Leads, Body 2x1.3mm, Pitch 0.65mm, Lead Span 2.1mm, IPC Medium Density"
  rrect25% 0.85x0.4 smd: 1(-1.125,0.65) 2(-1.125,0) 3(-1.125,-0.65) 4(1.125,-0.65) 5(1.125,0.65)
  silkscreen extent -1.48,-1.02 0.55,1.1, body extent -1.14,-1 1.14,1, height 0.95
DCK0006A_N [mm] "SOT23, 6-Leads, Body 2x1.3mm, Pitch 0.65mm, Lead Span 2.1mm, IPC Medium Density"
  rrect25% 0.85x0.4 smd: 1(-1.125,0.65) 2(-1.125,0) 3(-1.125,-0.65) 4(1.125,-0.65) 5(1.125,0) 6(1.125,0.65)
  silkscreen extent -1.5,-1.09 0.51,1.09, body extent -1.14,-1 1.14,1, height 0.95
DDB0014A [mm] "SMD, 14-Leads, Body 3.9x9.9mm, Pitch 1.27mm"
  rrect17% 1.55x0.6 smd: 1(-2.7,4.445) 3(-2.7,1.905) 4(-2.7,0.635) 5(-2.7,-0.635) 6(-2.7,-1.905) 7(-2.7,-3.175) 8(-2.7,-4.445) 9(2.7,-4.445) 10(2.7,-3.175) 11(2.7,-1.905) 12(2.7,-0.635) 14(2.7,1.905) 15(2.7,3.175) 16(2.7,4.445)
  silkscreen extent -3.5,-5 2,5, body extent -3.01,-4.95 3.01,4.95, height 1.75
DDPAK [mil] "D2-PAK, 3-Pads, Body 9.7x10.4mm (max), TO-263AB, using Vishay Silionix recommended pad sizes"
  rrect8% 135x49.49 smd: 1(-246.06,100) 3(-246.06,-100)
  rrect1% 355x420 smd paste-181.1: 4(155.51,0)
  silkscreen extent -295,-220 344,220, body extent -295,-202 324,202, height 180
DE1_600x400x900 [mm] "TH, 2-Leads, Dia 6mm, Lead Spacing 10mm"
  round 1.35 hole 0.9: 1(-5,0) 2(5,0)
  silkscreen extent -3,-1.65 3,1.65, body extent -5.35,-2 5.35,2, height 9
DIP-4 [mm] "DIP, 4-Leads, Body 6.86x4.83mm, Pitch 2.54mm"
  rect 1.15x1.15 hole 0.65: 1(-3.81,1.27)
  round 1.15 hole 0.65: 2(-3.81,-1.27) 3(3.81,-1.27) 4(3.81,1.27)
  silkscreen extent -4,-2.41 3.43,2.52, body extent -4.02,-2.41 4.02,2.41, height 5.59
DPAK [mm] "D-PAK, 3-Pads, Body 6.22x6.73mm (max), TO-252AA using nominal STEP model"
  rrect6% 2.6x1.6 smd: 1(-3.4,2.28) 3(-3.4,-2.28)
  rrect2% 6.2x5.8 smd paste-2.9: 4(3.4,0)
  silkscreen extent -4.5,-3.3 4.7,3.28, body extent -3.86,-3.29 5.84,3.29, height 2.48
DQJ0008A [mm] "SMD, 8-Leads, Body 5.75x4.9mm"
  rrect39% 0.91x0.51 smd paste-0.05 mask-0.05: 1(-2.795,1.905) 2(-2.795,0.635) 3(-2.795,-0.635) 4(-2.795,-1.905) 5(2.795,-1.905) 6(2.795,-0.635) 7(2.795,0.635) 8(2.795,1.905)
  rrect8% 1.58x1.25 on Bottom Paste: 9(-0.38,-1.45) 9(-0.38,0) 9(-0.38,1.45) 9(1.4,-1.45) 9(1.4,0) 9(1.4,1.45)
  rrect3% 3.48x4.47 on Bottom Solder: 9(0.55,0)
  rrect2% 4.49x4.57 smd paste-2.5 mask-2.5: 9(1.005,0)
  silkscreen extent -3,-2.6 3,2.6, body extent -3.13,-2.45 3.13,2.45, height 1.15
FUSE_372 [mm] "LITTELFUSE"
  round 1.5 hole 1: 1(-2.54,0) 2(2.54,0)
  silkscreen extent -4.25,-4.25 4.25,4.25, body extent -4.25,-4.25 4.25,4.25, height 8
HW_1250x2000 [mm] "TH, 2-Leads, Dia 12.5, Pin Spacing 5mm"
  rect 1.35x1.35 hole 0.85: 1(-2.5,0)
  round 1.35 hole 0.85: 2(2.5,0)
  silkscreen extent -6.5,-6.5 6.5,6.5, body extent -6.45,-6.49 6.51,6.49, height 22
HXG_2200x4500 [mm] "TH, 2-Leads, Dia 22mm, Pin Spacing 10mm"
  rect 2.5x2.5 hole 2: 1(-5,0)
  round 2.5 hole 2: 2(5,0)
  silkscreen extent -11.5,-11.5 11.5,11.5, body extent -11.5,-11.49 11.51,11.49, height 47.01
IND_7447020 [mm] "WURTH ELEKTRONIK"
  round 1.25 hole 0.75: 1(-3.5,0) 2(3.5,0)
  silkscreen extent -3.8,-7.9 3.8,7.9, body extent -3.8,-7.84 3.75,7.9, height 15.78
Keystone5000 [mil] "For Keystone 500x miniature loop terminals"
  round 80 hole 40: 1(0,0)
  silkscreen extent -52,-52 52,52, body extent -49,-49 49,49, height 182
Keystone5001 [mil] "For Keystone 500x miniature loop terminals"
  round 80 hole 40: 1(0,0)
  silkscreen extent -52,-52 52,52, body extent -49,-49 49,49, height 182
Keystone5010 [mil] "Keystone Multipurpose loops"
  round 87 hole 63: 1(0,0)
  silkscreen extent -70,-70 70,70, body extent -63,-63 63,62, height 319
Keystone5011 [mil] "Keystone Multipurpose loops"
  round 87 hole 63: 1(0,0)
  silkscreen extent -70,-70 70,70, body extent -63,-63 63,62, height 319
Keystone5012 [mil] "Keystone Multipurpose loops"
  round 87 hole 63: 1(0,0)
  silkscreen extent -70,-70 70,70, body extent -63,-63 63,62, height 319
MPK_1800x650 [mm] "TH, 2-Leads, Body 18x6.5mm, Lead Spacing 15mm"
  round 1.35 hole 0.85: 1(-7.5,0) 2(7.5,0)
  silkscreen extent -9,-3.25 9,3.25, body extent -9,-3.25 9,3.25, height 12
NHG_500x1100 [mm] "TH, 2-Leads, Dia 5mm,  Lead Spacing 2mm"
  rect 1.35x1.35 hole 0.85: 1(-1,0)
  round 1.35 hole 0.85: 2(1,0)
  silkscreen extent -2.75,-2.75 2.75,2.75, body extent -2.73,-2.75 2.75,2.75, height 12.51
On-Shore_ED120_4DS [mm] "ONSHORE"
  rrect5% 2x2 hole 1.25: 1(-7.62,0)
  round 2 hole 1.25: 2(-2.54,0) 3(2.54,0) 4(7.62,0)
  silkscreen extent -10.68,-4 10.16,5, body extent -10.86,-4 10.16,5, height 13
PS_1000x1250 [mm] "United Chemi-Con"
  rect 1.45x1.45 hole 0.85: 1(-2.5,0)
  round 1.45 hole 0.85: 2(2.5,0)
  silkscreen extent -5.25,-5.25 5.25,5.25, body extent -5.25,-5.24 5.25,5.24, height 14.01
SMA [mm] "Molded Diode, 2-Leads, Body 4.3x2.6mm, IPC Medium Density, based on OnSemi component dimensions and land pattern"
  rect 2x2 smd: 1(-2,0) 2(2,0)
  silkscreen extent -3.66,-1.57 2.79,1.57, body extent -2.6,-1.3 2.6,1.3, height 2.42
SMAF [mm] "SMD, 2-Leads, Body 3.8x2.5mm"
  rect 1.24x1.89 smd: 1(-2.04,0) 2(2.04,0)
  silkscreen extent -3.4,-1.3 2.8,1.3, body extent -2.35,-1.25 2.35,1.25, height 1
SMB [mil] "Molded Diode, 2-Leads, Body 5.4x3.6mm, IPC Medium Density, based on OnSemi component dimensions"
  rect 85x107.99 smd: 1(-87.01,0) 2(87.01,0)
  silkscreen extent -155,-82 125,82, body extent -106,-71 106,71, height 91
SMC [mil] "Molded Diode, 2-Leads, Body 6.9x5.8mm, IPC Medium Density, based on OnSemi component dimensions and land patterns"
  rect 110x150 smd: 1(-140.49,0) 2(140.49,0)
  silkscreen extent -221,-124 189,123, body extent -156,-116 156,116, height 91
SOD-123 [mm] "On Semi recommended land pattern"
  rect 0.915x1.22 smd: 1(-1.637,0) 2(1.637,0)
  silkscreen extent -2.74,-1.17 2.03,1.17, body extent -1.93,-0.9 1.93,0.9, height 1.35
SOD-123FL [mm] "Copied from SOD-123"
  rect 0.915x1.22 smd: 1(-1.637,0) 2(1.637,0)
  silkscreen extent -2.74,-1.16 1.68,1.16, body extent -1.9,-0.9 1.9,0.9, height 1
SOD-323 [mm] "NXP recommended land pattern"
  rect 0.6x0.6 smd paste-0.05: 1(-1.1,0) 2(1.1,0)
  silkscreen extent -2.06,-0.86 1.53,0.86, body extent -1.3,-0.67 1.3,0.68, height 1.1
sod-323 [mm] "NXP recommended land pattern"
  rect 0.6x0.6 smd paste-0.05: 1(-1.1,0) 2(1.1,0)
  silkscreen extent -2.06,-0.86 1.53,0.86, body extent -1.3,-0.67 1.3,0.68, height 1.1
SOD-523 [mm] "NXP Semiconductor recommended land pattern, nominal STEP model"
  rect 0.8x0.6 smd paste-0.05: 1(-0.55,0) 2(0.55,0)
  silkscreen extent -1.65,-0.66 1.2,0.66, body extent -0.8,-0.4 0.8,0.4, height 0.72
SOT-23 [mm] "SOT23, 3-Leads, Body 2.9x1.3mm, Pitch 0.95mm, Lead Span 2.5mm, IPC Medium Density"
  rrect50% 1x0.6 smd: 1(-1.2,0.95) 2(-1.2,-0.95) 3(1.2,0)
  silkscreen extent -1.63,-1.5 0.7,1.5, body extent -1.16,-1.45 1.21,1.45, height 1
THERM_B57236S0 [mm] "EPCOS"
  round 1.35 hole 0.85: 1(-2.5,0) 2(2.5,0)
  silkscreen extent -5.75,-3 5.75,3, body extent -5.75,-3 5.7,3, height 15.99
VAR_S10K275E2 [mm] "EPCOS"
  round 1.6 hole 1.1: 1(-5.585,1.1) 2(5.591,-1.1)
  silkscreen extent -6,-2.7 6,2.7, body extent -5.98,-2.7 5.98,2.7, height 14.99
WCAP-FTX2_1300x700x1200 [mm] "TH, 2-Leads, Body 13x7mm, Pin Spacing 10mm"
  round 1.4 hole 0.9: 1(-5,0) 2(5,0)
  silkscreen extent -6.5,-3.5 6.5,3.5, body extent -6.5,-3.5 6.5,3.5, height 12.05
WCAP-FTX2_1500x1000x1600 [mm] "TH, 2-Leads, Body 15x10mm, Pin Spacing 12.5mm"
  round 1.4 hole 0.9: 1(-6.25,0) 2(6.25,0)
  silkscreen extent -7.52,-5 7.48,5, body extent -7.5,-5 7.5,5, height 16
WE-CMB_M [mil] "Wurth"
  rect 70x70 hole 40: 1(-210.63,147.64)
  round 70 hole 40: 2(-210.63,-147.64) 3(210.63,-147.64) 4(210.63,147.64)
  silkscreen extent -335,-435 335,435, body extent -335,-394 335,394, height 1044
WE-CMB_XS [mm] "WE-CMB Series Size XS"
  rect 1.5x1.5 hole 0.9: 1(-5,2.25)
  round 1.5 hole 0.9: 2(-5,-2.25) 3(5,-2.25) 4(5,2.25)
  silkscreen extent -6.5,-3.75 6.5,3.75, body extent -6.5,-3.75 6.5,3.75, height 16.24
Wurth_ETD34 [mm] "TH, 12-Leads, Body 36x36mm, Pitch 5.5mm"
  round 1.8 hole 1.2: 2(-14,8.25) 4(-14,-2.75) 5(-14,-8.25) 6(-14,-13.75) 8(14,-8.25) 9(14,-2.75) 10(14,2.75) 11(14,8.25)
  silkscreen extent -18,-18 18,18, body extent -17.5,-17.35 17.5,17.35, height 24.42

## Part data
C100 C110: library part CMP-0077651-2, "CAP, CERM, 100 pF, X1 440 VAC/Y1 250 VAC, +/- 10%, B, D6xT4mm", Cap_Case=6x4x9mm, Manufacturer=MuRata, Supplier Part Number 1=490-16174-1-ND, TempCo=B, Tolerance_%=10%, ValueDisplayed=100pF
C101 C102 C111 C112: library part CMP-0077651-2, "CAP CER 220PF 250V RAD", Cap_Case=6x4x9mm, Manufacturer=MuRata, PartNumber=DE1B3RA221KN4AN01F, TempCo=B, Tolerance_%=10%, ValueDisplayed=220pF
C103: library part 450HXG180MEFCSN22X45, "CAP ALUM 100UF 20% 450V SNAP", Cap_Case=22x45mm, Manufacturer="United Chemi-Con", Tolerance_%=20, Value2=450V, ValueDisplayed=100µF
C104: library part 890324023025CS, "CAP, Film, 0.1 µF, X2 275 VAC, +/- 10%, TH", Cap_Case=13x7x12, Manufacturer="Wurth Elektronik", Tolerance_%=10, ValueDisplayed=0.1µF
C105: library part 890324023025CS, "CAP, Film, 0.22 µF, X2 275 VAC, +/- 10%, TH", Cap_Case=13x7x12, Manufacturer="Wurth Elektronik", Tolerance_%=10, ValueDisplayed=0.22µF
C106: "CAP, Film, 0.47 µF, X2 275 VAC, +/- 10%, TH", Cap_Case=15x10x16mm, Manufacturer="Wurth Elektronik", Supplier Part Number 1=732-5890-ND, Tolerance_%=10, ValueDisplayed=0.47µF
C107: library part 450MPK474J, "0.22µF ±10% Film Capacitor 450V Polypropylene (PP), Metallized Radial", Cap_Case=18x6.5mm, Manufacturer="Panasonic Electronic Components", Supplier Part Number 1=P16713-ND, Tolerance_%=5, Value1=Unknown, Value2=450V, ValueDisplayed=0.22µF
C108: "CAP, Film, 0.47 µF, 450 V, +/- 5%, TH", Cap_Case=18x6.5mm, Manufacturer=Rubycon, Supplier Part Number 1=1189-1824-ND, Tolerance_%=5, Value1=Unknown, Value2=450V, ValueDisplayed=0.47µF
C109: "CAP, CERM, 10 pF, 1000 V,+/- 5%, C0G/NP0, 0805", Cap_Case=0805, Manufacturer=Vishay-Vitramon, Supplier Part Number 1=720-1070-1-ND, TempCo=C0G/NP0, Tolerance_%=5, Value1=Unknown, Value2=1000V, ValueDisplayed=10pF
C113: "CAP, CERM, 0.1 µF, 25 V,+/- 10%, X5R, 0603", Cap_Case=0603, Manufacturer=MuRata, Supplier Part Number 1=GRM188R61E104KA01D-ND, TempCo=X5R, Tolerance_%=10, Value2=25V, ValueDisplayed=0.1µF
C114: "CAP, CERM, 3300 pF, 100 V,+/- 5%, X7R, 0603", Cap_Case=0603, Manufacturer=AVX, Supplier Part Number 1=478-3708-1-ND, TempCo=X7R, Tolerance_%=5, Value1="0.159 ohm", Value2=100V, ValueDisplayed=3300pF
C115: "CAP, CERM, 680 pF, 50 V,+/- 5%, C0G/NP0, 0603", Cap_Case=0603, Manufacturer=MuRata, Supplier Part Number 1=490-1447-1-ND, TempCo=C0G/NP0, Tolerance_%=5, Value2=50V, ValueDisplayed=680pF
C116: "CAP, CERM, 0.01 µF, 16 V,+/- 10%, X7R, 0603", Cap_Case=0603, Manufacturer="Wurth Elektronik", Supplier Part Number 1=732-7959-1-ND, TempCo=X7R, Tolerance_%=10, Value2=16V, ValueDisplayed=0.01µF
C117: "CAP, CERM, 0.47 µF, 25 V,+/- 10%, X5R, 0805", Cap_Case=0805, Manufacturer=AVX, Supplier Part Number 1=478-1407-1-ND, TempCo=X5R, Tolerance_%=10, Value1="0.017 ohm", Value2=25V, ValueDisplayed=0.47µF
C118: "CAP, CERM, 1 µF, 25 V,+/- 10%, X7R, 0603", Cap_Case=0603, Manufacturer=Kemet, Supplier Part Number 1=399-7376-1-ND, TempCo=X7R, Tolerance_%=10, Value2=25V, ValueDisplayed=1µF
C119: "CAP, AL, 10 µF, 50 V, +/- 20%, TH", Cap_Case=5x11mm, Manufacturer=Panasonic, Supplier Part Number 1=P5567-ND, Tolerance_%=20, Value2=50V, ValueDisplayed=10µF
C120: "CAP, CERM, 0.033 µF, 25 V,+/- 5%, X7R, 0603", Cap_Case=0603, Manufacturer=Kemet, Supplier Part Number 1=399-9068-1-ND, TempCo=X7R, Tolerance_%=5, Value2=25V, ValueDisplayed=0.033µF
C121: "CAP, CERM, 0.47 µF, 50 V,+/- 10%, X7R, AEC-Q200 Grade 1, 1206", Cap_Case=1206, Manufacturer=TDK, Supplier Part Number 1=445-5700-1-ND, TempCo=X7R, Tolerance_%=10, Value1="0.009426 ohm", Value2=50V, ValueDisplayed=0.47µF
